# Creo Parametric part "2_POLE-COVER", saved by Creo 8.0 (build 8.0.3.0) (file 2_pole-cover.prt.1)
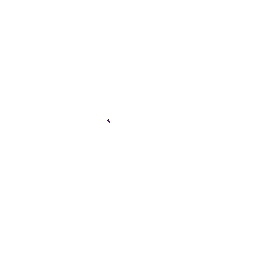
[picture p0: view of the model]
Units: millimeter Newton Second (mmNs); MM, TONNE, SECS

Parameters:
  SMT_DFLT_BEND_REL_LENGTH_TYPE = "Through All"

Other parameters: SMT_THICKNESS, SMT_PART_BEND_ALLOWANCE_FACTOR, SMT_DFLT_BEND_RADIUS, SMT_DFLT_BEND_ANGLE, SMT_DFLT_CRNR_REL_WIDTH, SMT_DFLT_CRNR_REL_DEPTH, SMT_DFLT_BEND_REL_WIDTH, SMT_DFLT_BEND_REL_DEPTH, SMT_DFLT_BEND_REL_LENGTH, SMT_DFLT_BEND_REL_ANGLE, SMT_GAP, SMT_DFLT_EDGE_TREA_WIDTH, SMT_DFLT_MITER_CUT_WIDTH, SMT_DFLT_MITER_CUT_OFFSET

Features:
  1. datum plane "DTM1"
  2. datum plane "DTM2"
  3. datum plane "DTM3"
  4. coordinate system
  5. protrusion
  6. datum plane "DTM6"
  7. protrusion
  8. round
  9. cut
  10. protrusion
  11. datum plane "DTM7"
  12. datum plane "DTM8"

Other named items: CS0

Layers: 0_ALL_AXIS, 0_ALL_CSYS, 0_ALL_CURVES, 0_ALL_PLANES, 0_ALL_POINTS, 0_ALL_SURFS, POLE-COVER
